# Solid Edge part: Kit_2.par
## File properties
Sűrűség: 0,000 kg/m^3
Pontosság: 0,990
Author: bmolnar
Last saved by: bmolnar
Revision: 79
Username: bmolnar
Dokumentum tartalom típus: 0
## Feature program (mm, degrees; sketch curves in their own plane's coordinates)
base feature "unnamed BaseFeature 1"
sketch for "Furat_1" plane through (-20.15, 0, 96.65) normal (1, 0, 0) x-axis (0, -1, 0)
  hole centre (0, 15.15) bore radius 2.067
hole "Furat_1" nominal diameter 5 finite  ThreadDepth = 5 mm; StartChamferOffset = 0.6 mm; StartChamferAngle = 45 deg
sketch for "Furat_2" plane through (-13, -13, 83.9) normal (0, 0, 1) x-axis (0, 1, 0)
  hole centre (0, 0) bore radius 2.067
hole "Furat_2" nominal diameter 5
sketch for "unnamed Hole 1" plane through (-13, -13, 83.9) normal (0, 0, 1) x-axis (0, 1, 0)
  hole centre (26, 0) bore radius 2.067
hole "unnamed Hole 1"
sketch for "unnamed Hole 2" plane through (-13, -13, 83.9) normal (0, 0, 1) x-axis (0, 1, 0)
  hole centre (26, -26) bore radius 2.067
hole "unnamed Hole 2"
sketch for "unnamed Hole 3" plane through (-13, -13, 83.9) normal (0, 0, 1) x-axis (0, 1, 0)
  hole centre (0, -26) bore radius 2.067
hole "unnamed Hole 3"
pattern "unnamed Pattern 1" of "Furat_2", "unnamed Hole 1", "unnamed Hole 2", "unnamed Hole 3"
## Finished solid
Body 1: solid body, 265 faces, 630 edges, 376 vertices, 3 internal voids.
  Faces by surface: plane 132, cylinder 56, swept 42, cone 26, torus 9
  Edges by curve: line 381, circle 155, spline 88, curve on surface 5, ellipse 1
Bounding box of the edges (mm; curved faces can reach further): 40.300 x 40.300 x 12.500, from (-20.15, -20.15, 76.5) to (20.15, 20.15, 89).
Cylindrical faces by radius (mm): R0.2 x18, R0.4246 x1, R0.4865 x1, R2.067 x5, R3.75 x2, R4 x4, R4.1 x12, R5.24 x1, R5.45 x2, R5.55 x2, R5.7 x1, R6 x1, R6.92 x1, R7 x1, R13.75 x4
Conical faces (half-angle, radius in mm at the cone's reference point): 0.5 deg R5 x4, 3 deg R6.96 x1, 7 deg R6.4156 x1, 14 deg R5.12 x1, 14 deg R5.3801 x1, 17 deg R5.12 x1, 23 deg R5.7369 x1, 42.5 deg R5.1096 x1, 45 deg R2.317 x2, 45 deg R2.367 x2, 45 deg R2.667 x1, 45 deg R4.25 x2, 45 deg R5.3 x2, 45 deg R5.35 x2, 45 deg R5.85 x1, 84 deg R5.4096 x1, 85 deg R6.73 x1, 87 deg R5.1371 x1
Toroidal faces (ring radius, tube radius in mm): R3.8 r0.2 x2, R4.4 r0.4 x2, R5.6606 r0.18 x1, R6.1131 r0.26 x1, R6.72 r0.2 x1, R9.4957 r0.5 x1, R11.0043 r0.5 x1
Planar faces by outward normal: +x 5, +y 16, +z 17, -x 7, -y 13, -z 5, oblique 69
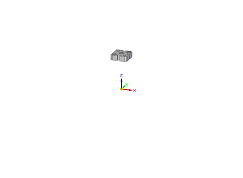
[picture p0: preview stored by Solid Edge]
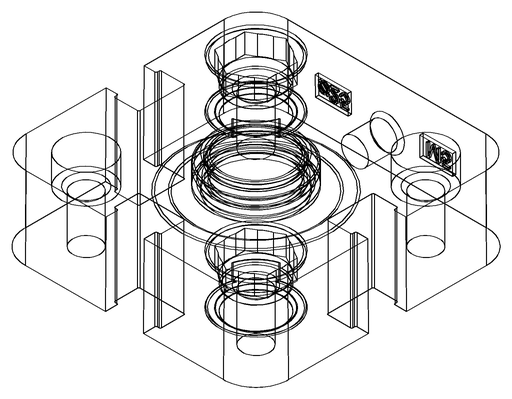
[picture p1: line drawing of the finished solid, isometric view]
